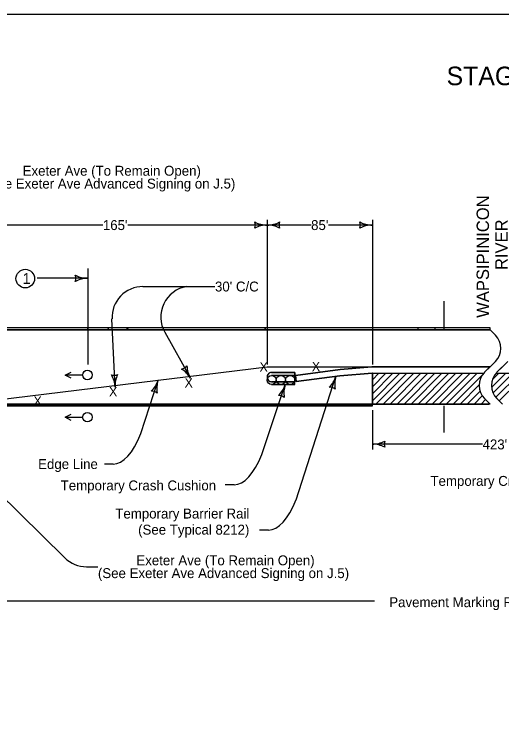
# Model space of a CAD drawing. Extents: x -2134934 to -2122394, y -2140205 to -2137036.
# Drawn here: x -2129448 to -2128661, y -2138192 to -2137036 of the extents above; entities that cross this region are included whole.
import ezdxf

# ---------------------------------------------------------------- set-up
doc = ezdxf.new("R2010")
doc.units = 0
for name, color, linetype in [('Barrier', 7, 'Continuous'), ('BridgeSuperStructureExisting', 7, 'Continuous'), ('Default', 7, 'Continuous'), ('dsnCellsNorthArrow', 7, 'Continuous'), ('DsnShtInsideBorder', 7, 'Continuous'), ('DsnShtPlotIdentification', 7, 'Continuous'), ('DsnShtPlotShape', 7, 'Continuous')]:
    doc.layers.add(name, color=color, linetype=linetype)

msp = doc.modelspace()

# ---------------------------------------------------------------- linework, layer by layer
at = {"layer": 'BridgeSuperStructureExisting'}
for p, q in [((-2129039.8, -2137367.6), (-2129039.8, -2137601.1)), ((-2128870.1, -2137367.6), (-2128870.1, -2137601.1)), ((-2129305.2, -2137376.2), (-2129530.1, -2137376.2)), ((-2129039.8, -2137376.2), (-2129264.7, -2137376.2)), ((-2128969, -2137376.2), (-2129039.8, -2137376.2)), ((-2128870.1, -2137376.2), (-2128940.9, -2137376.2)), ((-2129329.6, -2137446.2), (-2129329.6, -2137601.1)), ((-2129329.6, -2137462.1), (-2129411.4, -2137462.1)), ((-2129240.5, -2137475.4), (-2129124.2, -2137475.4)), ((-2128754.7, -2137498.8), (-2128754.7, -2137545.2)), ((-2129285.4, -2137637.7), (-2129290.5, -2137527.7)), ((-2128680.1, -2137545.2), (-2130182.6, -2137545.2)), ((-2129205.4, -2137549.2), (-2129163.9, -2137623.4)), ((-2128680.1, -2137545.2), (-2128671.3, -2137553.9)), ((-2128671.3, -2137553.9), (-2128680.1, -2137545.2)), ((-2128671.3, -2137596.4), (-2128688.9, -2137613.9)), ((-2128651.3, -2137596.4), (-2128668.9, -2137613.9)), ((-2129530.1, -2137665.2), (-2129039.8, -2137605.2)), ((-2129039.8, -2137605.2), (-2128870.7, -2137605.2)), ((-2128922.2, -2137609.5), (-2128994.2, -2137618.8)), ((-2128994.2, -2137618.8), (-2128922.2, -2137609.5)), ((-2128994.2, -2137618.8), (-2128922.2, -2137609.5)), ((-2128870.7, -2137605.2), (-2128922.2, -2137609.5)), ((-2128922.2, -2137609.5), (-2128870.7, -2137605.2)), ((-2128922.2, -2137609.5), (-2128870.7, -2137605.2)), ((-2128680.1, -2137605.2), (-2128870.7, -2137605.2)), ((-2128870.7, -2137605.2), (-2128680.1, -2137605.2)), ((-2128870.7, -2137605.2), (-2128680.1, -2137605.2)), ((-2128688.9, -2137613.9), (-2128680.1, -2137605.2)), ((-2128660.1, -2137605.2), (-2128668.9, -2137613.9)), ((-2129337.9, -2137618.6), (-2129365.8, -2137618.6)), ((-2129032.7, -2137614.1), (-2128995.2, -2137614.1)), ((-2128995.2, -2137618.8), (-2129032.7, -2137618.8)), ((-2128995.2, -2137614.1), (-2128995.2, -2137629.1)), ((-2128995.2, -2137633.8), (-2128995.2, -2137618.8)), ((-2128994.2, -2137618.8), (-2128992.9, -2137628.7)), ((-2128992.9, -2137628.7), (-2128994.2, -2137618.8)), ((-2128992.9, -2137628.7), (-2128994.2, -2137618.8)), ((-2128993.3, -2137819.5), (-2128928.9, -2137620.3)), ((-2128992.9, -2137628.7), (-2128922.4, -2137619.5)), ((-2128922.4, -2137619.5), (-2128992.9, -2137628.7)), ((-2128922.4, -2137619.5), (-2128992.9, -2137628.7)), ((-2128922.4, -2137619.5), (-2128870.3, -2137615.2)), ((-2128870.3, -2137615.2), (-2128922.4, -2137619.5)), ((-2128870.1, -2137615.2), (-2128922.4, -2137619.5)), ((-2128870.3, -2137615.2), (-2128690.1, -2137615.2)), ((-2128870.3, -2137615.2), (-2128690.1, -2137615.2)), ((-2128825.6, -2137615.2), (-2128870.1, -2137659.7)), ((-2128870.1, -2137615.2), (-2128870.1, -2137665.2)), ((-2128836.9, -2137615.2), (-2128870.1, -2137648.4)), ((-2128848.2, -2137615.2), (-2128870.1, -2137637.1)), ((-2128859.5, -2137615.2), (-2128870.1, -2137625.8)), ((-2128870.1, -2137665.2), (-2128870.1, -2137615.2)), ((-2128814.3, -2137615.2), (-2128864.3, -2137665.2)), ((-2128802.9, -2137615.2), (-2128852.9, -2137665.2)), ((-2128791.6, -2137615.2), (-2128841.6, -2137665.2)), ((-2128780.3, -2137615.2), (-2128830.3, -2137665.2)), ((-2128769, -2137615.2), (-2128819, -2137665.2)), ((-2128757.7, -2137615.2), (-2128807.7, -2137665.2)), ((-2128746.4, -2137615.2), (-2128796.4, -2137665.2)), ((-2128735.1, -2137615.2), (-2128785.1, -2137665.2)), ((-2128723.8, -2137615.2), (-2128773.8, -2137665.2)), ((-2128712.4, -2137615.2), (-2128762.4, -2137665.2)), ((-2128701.1, -2137615.2), (-2128751.1, -2137665.2)), ((-2128691.3, -2137616.6), (-2128739.8, -2137665.2)), ((-2128654.4, -2137615.2), (-2128677.5, -2137638.3)), ((-2128665.7, -2137615.2), (-2128676.1, -2137625.6)), ((-2128643.1, -2137615.2), (-2128675.1, -2137647.2)), ((-2128631.8, -2137615.2), (-2128670.8, -2137654.2)), ((-2128670.1, -2137615.2), (-2128470.5, -2137615.2)), ((-2128670.1, -2137615.2), (-2128470.1, -2137615.2)), ((-2128620.4, -2137615.2), (-2128665.3, -2137660)), ((-2129243.9, -2137712.8), (-2129216.1, -2137626.7)), ((-2129048.7, -2137746.4), (-2129010.8, -2137633.8)), ((-2128995.2, -2137629.1), (-2129032.7, -2137629.1)), ((-2129032.7, -2137633.8), (-2128995.2, -2137633.8)), ((-2128697.7, -2137634.3), (-2128728.5, -2137665.2)), ((-2128696.3, -2137644.3), (-2128717.2, -2137665.2)), ((-2128692.6, -2137651.9), (-2128705.9, -2137665.2)), ((-2128687.3, -2137657.9), (-2128694.6, -2137665.2)), ((-2128688.9, -2137656.4), (-2128680.1, -2137665.2)), ((-2128668.9, -2137656.4), (-2128660.1, -2137665.2)), ((-2130182.6, -2137665.2), (-2128870.1, -2137665.2)), ((-2128754.7, -2137668.2), (-2128754.7, -2137710.9)), ((-2128870.1, -2137675.2), (-2128870.1, -2137738.5)), ((-2129337.9, -2137686.6), (-2129365.8, -2137686.6)), ((-2129366.8, -2137913.4), (-2129580.8, -2137702.6)), ((-2128692.2, -2137729.8), (-2128870.1, -2137729.8)), ((-2129288.6, -2137762), (-2129302.8, -2137762)), ((-2129093.4, -2137795.5), (-2129107.7, -2137795.5)), ((-2129038, -2137868.7), (-2129052.2, -2137868.7)), ((-2129331.7, -2137927.8), (-2129313.2, -2137927.8)), ((-2128866.5, -2137983.3), (-2129530.1, -2137983.3))]:
    msp.add_line(p, q, dxfattribs=at)
for points in [[(-2128680.1, -2137605.2), (-2128680.1, -2137605.2), (-2128671.3, -2137596.4)], [(-2129356.2, -2137623.4), (-2129366.2, -2137618.4), (-2129356.2, -2137613.4)], [(-2128690.1, -2137615.2), (-2128690.1, -2137615.2)], [(-2128680.1, -2137665.2), (-2128870.1, -2137665.2)], [(-2129356.2, -2137691.5), (-2129366.2, -2137686.5), (-2129356.2, -2137681.5)]]:
    msp.add_lwpolyline(points, dxfattribs=at)
for centre, radius in [((-2129430.5, -2137462.6), 15), ((-2129330.1, -2137618.2), 7.74), ((-2129032.7, -2137626.3), 7.5), ((-2129032.7, -2137626.3), 7.5), ((-2129017.7, -2137626.3), 7.5), ((-2129017.7, -2137626.3), 7.5), ((-2129002.7, -2137626.3), 7.5), ((-2129002.7, -2137626.3), 7.5), ((-2129330.1, -2137686.3), 7.74)]:
    msp.add_circle(centre, radius, dxfattribs=at)
for centre, radius, start, end in [((-2129365.3, -2137462.1), 16.4, 342.2666, 17.7334), ((-2129329.6, -2137419.6), 42.5, 241.9275, 270), ((-2129329.6, -2137504.6), 42.5, 90, 118.0725), ((-2129240.5, -2137525.4), 50, 90, 182.6154), ((-2129161.7, -2137524.8), 50.1, 99.6171, 209.1999), ((-2128692.5, -2137575.2), 30, 315, 45), ((-2128692.5, -2137575.2), 30, 315, 45), ((-2129032.7, -2137621.6), 7.5, 89.9996, 270), ((-2128667.7, -2137635.2), 30, 135, 225), ((-2128667.7, -2137635.2), 30, 135, 138.2713), ((-2128647.7, -2137635.2), 30, 135, 225), ((-2128647.7, -2137635.2), 30, 135, 138.1884), ((-2128870.1, -2137687.4), 42.5, 270, 298.0725), ((-2128834.5, -2137729.8), 16.4, 162.2666, 197.7334), ((-2128870.1, -2137772.3), 42.5, 61.9275, 90), ((-2129331.7, -2137877.8), 50, 225.4365, 270)]:
    msp.add_arc(centre, radius, start, end, dxfattribs=at)
for centre in [(-2129288.6, -2137549.1), (-2129093.4, -2137582.6), (-2129038, -2137655.7)]:
    msp.add_ellipse(centre, major_axis=(0, -212.9), ratio=0.328743, start_param=0, end_param=0.693162, dxfattribs=at)
at = {"layer": 'Default'}
msp.add_lwpolyline([(-2130232, -2137035.9), (-2127097, -2137035.9), (-2127097, -2139045.9), (-2130232, -2139045.9)], close=True, dxfattribs=at)
at = {"layer": 'DsnShtInsideBorder'}
for p, q in [((-2128995.2, -2137614.1), (-2129032.7, -2137614.1)), ((-2128995.2, -2137629.1), (-2128995.2, -2137614.1)), ((-2129032.7, -2137629.1), (-2128995.2, -2137629.1))]:
    msp.add_line(p, q, dxfattribs=at)
msp.add_arc((-2129032.7, -2137621.6), 7.5, 90.0024, 269.9972, dxfattribs=at)
at = {"layer": 'DsnShtPlotIdentification'}
for p, q in [((-2128680.1, -2137542.2), (-2130182.6, -2137542.2)), ((-2129329.6, -2137542.2), (-2129602.5, -2137542.2)), ((-2129329.6, -2137542.2), (-2129329.6, -2137545.2)), ((-2129296.4, -2137542.2), (-2129329.6, -2137542.2)), ((-2129329.6, -2137545.2), (-2129329.6, -2137542.2)), ((-2129266.6, -2137542.2), (-2129296.4, -2137542.2)), ((-2129296.4, -2137542.2), (-2129296.2, -2137545.2)), ((-2129296.2, -2137545.2), (-2129296.4, -2137542.2)), ((-2129266.6, -2137542.2), (-2129264.4, -2137545.2)), ((-2129043.1, -2137542.2), (-2129266.6, -2137542.2)), ((-2129264.4, -2137545.2), (-2129266.6, -2137542.2)), ((-2128796.1, -2137542.2), (-2129043.1, -2137542.2)), ((-2129043.1, -2137542.2), (-2129043.1, -2137545.2)), ((-2129043.1, -2137545.2), (-2129043.1, -2137542.2)), ((-2128769.2, -2137542.2), (-2128796.1, -2137542.2)), ((-2128680.1, -2137542.2), (-2128769.2, -2137542.2)), ((-2128680.1, -2137545.2), (-2128680.1, -2137542.2)), ((-2128680.1, -2137545.2), (-2130182.6, -2137545.2)), ((-2129603.5, -2137545.2), (-2129329.6, -2137545.2)), ((-2129329.6, -2137545.2), (-2129296.2, -2137545.2)), ((-2129296.2, -2137545.2), (-2129264.4, -2137545.2)), ((-2129264.4, -2137545.2), (-2129043.1, -2137545.2)), ((-2129043.1, -2137545.2), (-2128797, -2137545.2)), ((-2128797, -2137545.2), (-2128768.2, -2137545.2)), ((-2128768.2, -2137545.2), (-2128680.1, -2137545.2)), ((-2130182, -2137665.2), (-2128682, -2137665.2)), ((-2129497.6, -2137668.2), (-2129183.9, -2137668.2)), ((-2129182.9, -2137665.2), (-2129475.9, -2137665.2)), ((-2129183.9, -2137668.2), (-2129182.9, -2137665.2)), ((-2129182.9, -2137665.2), (-2129183.9, -2137668.2)), ((-2129183.9, -2137668.2), (-2129023.4, -2137668.2)), ((-2129022.5, -2137665.2), (-2129182.9, -2137665.2)), ((-2129023.4, -2137668.2), (-2129022.5, -2137665.2)), ((-2129022.5, -2137665.2), (-2129023.4, -2137668.2)), ((-2129023.4, -2137668.2), (-2128944.3, -2137668.2)), ((-2128943.4, -2137665.2), (-2129022.5, -2137665.2)), ((-2128944.3, -2137668.2), (-2128943.4, -2137665.2)), ((-2128943.4, -2137665.2), (-2128944.3, -2137668.2)), ((-2128944.3, -2137668.2), (-2128870.1, -2137668.2)), ((-2128870.8, -2137665.2), (-2128943.4, -2137665.2)), ((-2128870.1, -2137665.2), (-2128870.8, -2137665.2)), ((-2128870.1, -2137668.2), (-2128870.1, -2137665.2)), ((-2128870.1, -2137668.2), (-2128870.1, -2137665.2))]:
    msp.add_line(p, q, dxfattribs=at)
for points in [[(-2130182.4, -2137545.2), (-2128872.4, -2137545.2)], [(-2128870.1, -2137665.2), (-2130182.6, -2137665.2)], [(-2128870.1, -2137668.2), (-2130182.6, -2137668.2)]]:
    msp.add_lwpolyline(points, dxfattribs=at)
for start, end in [(156.382, 168.6701), (156.382, 168.6701), (11.3299, 23.618), (11.3299, 23.618)]:
    msp.add_arc((-2128782.6, -2137548), 14.7, start, end, dxfattribs=at)
at = {"layer": 'DsnShtPlotShape'}
for centre, radius, start, end in [((-2129075.4, -2137376.2), 16.4, 342.2666, 17.7334), ((-2129039.8, -2137333.7), 42.5, 241.9275, 270), ((-2129039.8, -2137418.7), 42.5, 90, 118.0725), ((-2129039.8, -2137333.7), 42.5, 270, 298.0725), ((-2129039.8, -2137418.7), 42.5, 61.9275, 90), ((-2129004.2, -2137376.2), 16.4, 162.2666, 197.7334), ((-2128905.8, -2137376.2), 16.4, 342.2666, 17.7334), ((-2128870.1, -2137333.7), 42.5, 241.9275, 270), ((-2128870.1, -2137418.7), 42.5, 90, 118.0725), ((-2129181.5, -2137592.5), 16.4, 281.9035, 317.3702), ((-2129200.8, -2137644.5), 42.5, 29.6368, 57.7093), ((-2129126.9, -2137602.4), 42.5, 181.5643, 209.6368), ((-2129287.1, -2137602.2), 16.4, 254.8821, 290.3488), ((-2129327.9, -2137639.7), 42.5, 2.6154, 30.6879), ((-2129243, -2137635.8), 42.5, 154.5429, 182.6154), ((-2128969.3, -2137607.3), 42.5, 314.0124, 342.0849), ((-2128888.4, -2137633.4), 42.5, 162.0849, 190.1574), ((-2129256.5, -2137613.7), 42.5, 314.0124, 342.0849), ((-2129175.6, -2137639.8), 42.5, 162.0849, 190.1574), ((-2129051.2, -2137620.8), 42.5, 314.0124, 342.0849), ((-2128970.4, -2137646.9), 42.5, 162.0849, 190.1574), ((-2129227, -2137660.6), 16.4, 54.3516, 89.8183), ((-2128939.8, -2137654.2), 16.4, 54.3516, 89.8183), ((-2129021.8, -2137667.7), 16.4, 54.3516, 89.8183)]:
    msp.add_arc(centre, radius, start, end, dxfattribs=at)

# ---------------------------------------------------------------- texts
at = {"layer": 'Barrier'}
msp.add_text('STAGE 1', height=30, dxfattribs=at).set_placement((-2128750.3, -2137150.4))
at = {"layer": 'BridgeSuperStructureExisting'}
for s, height, p in [('Exeter Ave (To Remain Open)', 16, (-2129434.7, -2137296.5)), ('(See Exeter Ave Advanced Signing on J.5)', 16, (-2129496.9, -2137317.2)), ("165'", 16, (-2129305.2, -2137384.2)), ("85'", 16, (-2128969, -2137384.2)), ('1', 17.5, (-2129434.9, -2137471.3)), ("30' C/C", 16, (-2129124.2, -2137483.4)), ('X', 15, (-2129052.3, -2137612.7)), ('X', 15, (-2128967.8, -2137612.1)), ("423'", 16, (-2128692.2, -2137738.3)), ('Edge Line', 16, (-2129409.7, -2137770)), ('Temporary Crash Cushion', 16, (-2128776.3, -2137797.2)), ('Temporary Crash Cushion', 16, (-2129373.3, -2137804.5)), ('Temporary Barrier Rail', 16, (-2129285.1, -2137849.9)), ('(See Typical 8212)', 16, (-2129248.3, -2137875.9)), ('Exeter Ave (To Remain Open)', 16, (-2129251.1, -2137925.4)), ('(See Exeter Ave Advanced Signing on J.5)', 16, (-2129313.2, -2137946.1)), ('Pavement Marking Removal Limits', 16, (-2128842.8, -2137993))]:
    msp.add_text(s, height=height, dxfattribs=at).set_placement(p)
for p in [(-2129173.3, -2137638.4), (-2129295.3, -2137652.7), (-2129417.2, -2137667.5)]:
    msp.add_text('X', height=15, rotation=359.9652, dxfattribs=at).set_placement(p)
at = {"layer": 'dsnCellsNorthArrow'}
for s, p in [('WAPSIPINICON ', (-2128681.8, -2137525.9)), ('RIVER', (-2128651.8, -2137448.8))]:
    msp.add_text(s, height=20, rotation=90, dxfattribs=at).set_placement(p)

doc.saveas('drawing.dxf')
